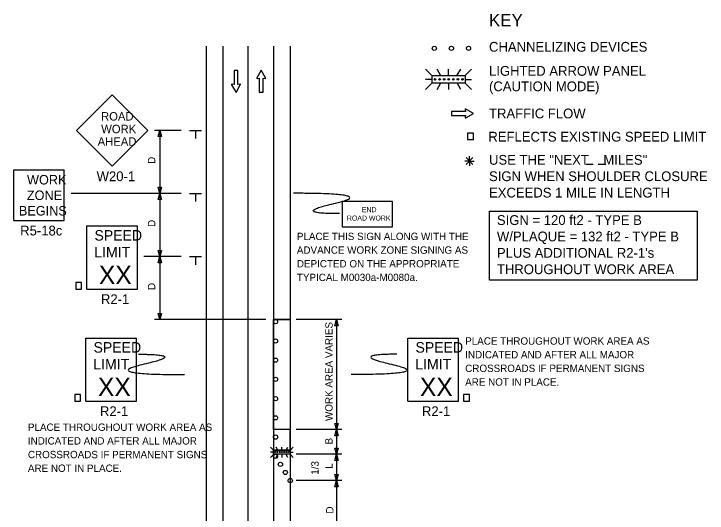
# Model space of a CAD drawing. Extents: x 16750 to 18471, y 7218 to 8211.
# Drawn here: x 16760 to 17420, y 7736 to 8211 of the extents above; entities that cross this region are included whole.
import ezdxf

# ---------------------------------------------------------------- set-up
doc = ezdxf.new("R2010")
doc.units = 0
for name, color, linetype in [('Level 6', 7, 'Continuous'), ('MT_SCRATCH_LEVEL_E', 7, 'Continuous'), ('PAVT_EDGE_EX', 7, 'Continuous'), ('TRAFFIC_SIGNS_PR', 7, 'Continuous'), ('TYPICAL_TEXT_DIMEN_EX', 7, 'Continuous'), ('TYPICAL_TEXT_DIMEN_PR', 7, 'Continuous')]:
    doc.layers.add(name, color=color, linetype=linetype)

msp = doc.modelspace()

# ---------------------------------------------------------------- linework, layer by layer
at = {"layer": 'Level 6'}
for points in [[(17191.74, 8091.59), (17197.33, 8091.59), (17197.33, 8097.76), (17191.74, 8097.76)], [(16819.11, 7949.45), (16824.71, 7949.45), (16824.71, 7955.62), (16819.11, 7955.62)], [(16818.21, 7842.9), (16823.8, 7842.9), (16823.8, 7849.07), (16818.21, 7849.07)], [(17188.08, 7842.9), (17193.67, 7842.9), (17193.67, 7849.07), (17188.08, 7849.07)]]:
    msp.add_lwpolyline(points, close=True, dxfattribs=at)
at = {"layer": 'MT_SCRATCH_LEVEL_E'}
for p, q in [((16973.41, 8157.34), (16969.67, 8157.34)), ((16969.67, 8157.34), (16969.67, 8144.08)), ((16973.41, 8157.34), (16969.67, 8157.34)), ((16969.67, 8157.34), (16969.67, 8144.08)), ((16973.41, 8144.08), (16973.41, 8157.34)), ((16973.41, 8144.08), (16973.41, 8157.34)), ((16995.57, 8157.71), (16991.46, 8150.47)), ((16995.57, 8157.71), (16991.46, 8150.47)), ((16999.72, 8150.47), (16995.57, 8157.71)), ((16999.72, 8150.47), (16995.57, 8157.71)), ((16967.42, 8143.72), (16971.56, 8136.47)), ((16967.42, 8143.72), (16971.56, 8136.47)), ((16969.67, 8144.08), (16967.9, 8144.4)), ((16969.67, 8144.08), (16967.9, 8144.4)), ((16971.56, 8136.47), (16975.67, 8143.72)), ((16971.56, 8136.47), (16975.67, 8143.72)), ((16975.19, 8144.4), (16973.41, 8144.08)), ((16975.19, 8144.4), (16973.41, 8144.08)), ((16991.94, 8149.79), (16993.72, 8150.1)), ((16991.94, 8149.79), (16993.72, 8150.1)), ((16993.72, 8150.1), (16993.72, 8136.85)), ((16993.72, 8150.1), (16993.72, 8136.85)), ((16997.46, 8136.85), (16997.46, 8150.1)), ((16997.46, 8150.1), (16999.24, 8149.79)), ((16997.46, 8136.85), (16997.46, 8150.1)), ((16997.46, 8150.1), (16999.24, 8149.79)), ((16993.72, 8136.85), (16997.46, 8136.85)), ((16993.72, 8136.85), (16997.46, 8136.85)), ((17189.75, 8118.42), (17176.5, 8118.42)), ((17176.5, 8118.42), (17176.5, 8114.68)), ((17189.75, 8118.42), (17176.5, 8118.42)), ((17176.5, 8118.42), (17176.5, 8114.68)), ((17189.44, 8120.2), (17189.75, 8118.42)), ((17189.44, 8120.2), (17189.75, 8118.42)), ((17197.36, 8116.57), (17190.12, 8120.68)), ((17197.36, 8116.57), (17190.12, 8120.68)), ((17176.5, 8114.68), (17189.75, 8114.68)), ((17176.5, 8114.68), (17189.75, 8114.68)), ((17189.75, 8114.68), (17189.44, 8112.9)), ((17189.75, 8114.68), (17189.44, 8112.9)), ((17190.12, 8112.42), (17197.36, 8116.57)), ((17190.12, 8112.42), (17197.36, 8116.57))]:
    msp.add_line(p, q, dxfattribs=at)
for centre, start, end in [((16991.87, 8150.25), 150.42484, 279.96381), ((16991.87, 8150.25), 150.42484, 279.96381), ((16999.31, 8150.25), 260.03619, 29.77312), ((16999.31, 8150.25), 260.03619, 29.77312), ((16967.82, 8143.94), 80.03619, 209.77312), ((16967.82, 8143.94), 80.03619, 209.77312), ((16975.27, 8143.94), 330.42484, 99.96381), ((16975.27, 8143.94), 330.42484, 99.96381), ((17189.9, 8120.27), 60.42484, 189.96381), ((17189.9, 8120.27), 60.42484, 189.96381), ((17189.9, 8112.83), 170.03619, 299.77312), ((17189.9, 8112.83), 170.03619, 299.77312)]:
    msp.add_arc(centre, 0.463, start, end, dxfattribs=at)
at = {"layer": 'PAVT_EDGE_EX'}
for p, q in [((16943.15, 8180.56), (16943.15, 7445.4)), ((16959.15, 8180.56), (16959.15, 7445.4)), ((16983.15, 7383.56), (16983.15, 8180.56)), ((17007.15, 8180.56), (17007.15, 7445.4)), ((17023.15, 8180.56), (17023.15, 7445.4)), ((17007.15, 7815.82), (17007.15, 7920.41)), ((17007.15, 7920.41), (17023.15, 7920.41)), ((17023.15, 7920.41), (17023.15, 7815.82)), ((17023.15, 7815.82), (17007.15, 7815.82)), ((17023.15, 7815.82), (17007.15, 7815.82)), ((17007.15, 7815.82), (17007.15, 7796.12)), ((17023.15, 7796.12), (17023.15, 7815.82)), ((17007.15, 7796.12), (17023.15, 7796.12))]:
    msp.add_line(p, q, dxfattribs=at)
for points in [[(16983.15, 8145.4), (16983.15, 8170.4)], [(16983.15, 8045.4), (16983.15, 8070.4)], [(16983.15, 7945.4), (16983.15, 7970.4)], [(16983.15, 7845.4), (16983.15, 7870.4)], [(16983.15, 7745.4), (16983.15, 7770.4)]]:
    msp.add_lwpolyline(points, dxfattribs=at)
at = {"layer": 'TRAFFIC_SIGNS_PR'}
for p, q in [((17151.95, 8158.61), (17157.59, 8152.98)), ((17166.13, 8152.98), (17162.87, 8158.62)), ((17173.76, 8152.98), (17173.76, 8158.62)), ((17182.03, 8152.98), (17185.28, 8158.62)), ((17189.93, 8152.98), (17195.57, 8158.62)), ((17157.59, 8148.91), (17151.95, 8148.91)), ((17151.95, 8139.21), (17157.59, 8144.85)), ((17160.86, 8148.91), (17160.86, 8148.91)), ((17162.82, 8139.21), (17166.07, 8144.85)), ((17165.21, 8148.91), (17165.21, 8148.91)), ((17169.56, 8148.91), (17169.56, 8148.91)), ((17173.76, 8144.85), (17173.76, 8139.21)), ((17173.91, 8148.91), (17173.91, 8148.91)), ((17178.25, 8148.91), (17178.25, 8148.91)), ((17185.33, 8139.21), (17182.08, 8144.85)), ((17182.6, 8148.91), (17182.6, 8148.91)), ((17186.95, 8148.91), (17186.95, 8148.91)), ((17189.93, 8148.91), (17195.57, 8148.91)), ((17189.93, 8144.85), (17195.57, 8139.21)), ((16853.79, 8134.25), (16819.85, 8100.31)), ((16887.73, 8100.31), (16853.79, 8134.25)), ((16819.85, 8100.31), (16853.79, 8066.37)), ((16853.79, 8066.37), (16887.73, 8100.31)), ((16760.27, 8014.73), (16760.27, 8062.73)), ((16760.27, 8062.73), (16808.27, 8062.73)), ((16808.27, 8014.73), (16808.27, 8062.73)), ((16760.27, 8014.73), (16808.27, 8014.73)), ((16829.72, 8009.45), (16877.72, 8009.45)), ((16829.72, 7949.45), (16829.72, 8009.45)), ((16877.72, 7949.45), (16877.72, 8009.45)), ((16829.72, 7949.45), (16877.72, 7949.45)), ((17023.15, 7920.41), (17007.15, 7920.41)), ((17009.15, 7918.39), (17009.15, 7918.39)), ((16828.82, 7902.9), (16876.82, 7902.9)), ((16828.82, 7842.9), (16828.82, 7902.9)), ((16876.82, 7842.9), (16876.82, 7902.9)), ((17135.06, 7902.9), (17183.06, 7902.9)), ((17135.06, 7842.9), (17135.06, 7902.9)), ((17183.06, 7842.9), (17183.06, 7902.9)), ((16828.82, 7842.9), (16876.82, 7842.9)), ((17135.06, 7842.9), (17183.06, 7842.9)), ((17023.15, 7815.82), (17007.15, 7815.82)), ((17004.26, 7799.07), (17007.08, 7796.25)), ((17007.08, 7794.22), (17004.26, 7794.22)), ((17023.15, 7796.12), (17007.15, 7796.12)), ((17008.72, 7794.22), (17008.72, 7794.22)), ((17011.35, 7796.25), (17009.72, 7799.07)), ((17010.9, 7794.22), (17010.9, 7794.22)), ((17013.07, 7794.22), (17013.07, 7794.22)), ((17015.17, 7796.25), (17015.17, 7799.07)), ((17015.24, 7794.22), (17015.24, 7794.22)), ((17017.42, 7794.22), (17017.42, 7794.22)), ((17019.3, 7796.25), (17020.93, 7799.07)), ((17019.59, 7794.22), (17019.59, 7794.22)), ((17021.76, 7794.22), (17021.76, 7794.22)), ((17023.25, 7796.25), (17026.08, 7799.07)), ((17023.25, 7794.22), (17026.08, 7794.22)), ((17004.26, 7789.37), (17007.08, 7792.19)), ((17009.7, 7789.37), (17011.33, 7792.19)), ((17015.17, 7792.19), (17015.17, 7789.37)), ((17020.96, 7789.37), (17019.33, 7792.19)), ((17023.25, 7792.19), (17026.08, 7789.37))]:
    msp.add_line(p, q, dxfattribs=at)
for points in [[(17189.47, 8145.31), (17158.05, 8145.31), (17158.05, 8152.51), (17189.47, 8152.51)], [(17072.52, 8008.67), (17120.52, 8008.67), (17120.52, 8032.67), (17072.52, 8032.67)], [(17023.02, 7792.42), (17007.32, 7792.42), (17007.32, 7796.02), (17023.02, 7796.02)]]:
    msp.add_lwpolyline(points, close=True, dxfattribs=at)
for centre, radius in [((17160.15, 8178.49), 2), ((17176.45, 8178.49), 2), ((17192.75, 8178.49), 2), ((17160.9, 8148.91), 0.758), ((17165.21, 8148.91), 0.758), ((17169.56, 8148.91), 0.758), ((17173.9, 8148.91), 0.758), ((17178.25, 8148.91), 0.758), ((17182.6, 8148.91), 0.758), ((17186.95, 8148.91), 0.758), ((17009.15, 7918.39), 2), ((17009.15, 7900.1), 2), ((17009.15, 7881.81), 2), ((17009.15, 7863.53), 2), ((17009.15, 7845.24), 2), ((17009.15, 7826.96), 2), ((17009.15, 7808.67), 2), ((17008.74, 7794.22), 0.379), ((17010.89, 7794.22), 0.379), ((17013.07, 7794.22), 0.379), ((17015.24, 7794.22), 0.379), ((17017.42, 7794.22), 0.379), ((17019.59, 7794.22), 0.379), ((17021.76, 7794.22), 0.379), ((17009.14, 7790.38), 2), ((17009.15, 7790.39), 2), ((17013.81, 7782.69), 2), ((17018.48, 7774.99), 2), ((17023.15, 7767.3), 2)]:
    msp.add_circle(centre, radius, dxfattribs=at)
for points in [[(17069.87, 8021.22), (17022.64, 8021.22), (17107.66, 8040.56), (17026.18, 8040.56)], [(16878.89, 7887.45), (16926.12, 7887.45), (16841.1, 7868.11), (16922.58, 7868.11)], [(17124.66, 7887.45), (17077.43, 7887.45), (17162.45, 7868.11), (17080.97, 7868.11)]]:
    msp.add_open_spline(points, degree=2, dxfattribs=at)
at = {"layer": 'TYPICAL_TEXT_DIMEN_PR'}
for p, q in [((16919.43, 8100.41), (16894.15, 8100.41)), ((16897.58, 8094.55), (16899.15, 8100.41)), ((16899.15, 8100.41), (16900.73, 8094.55)), ((16899.15, 8100.41), (16899.15, 8040.41)), ((16927.47, 8100.41), (16938.72, 8100.41)), ((16933.1, 8100.41), (16933.1, 8092.63)), ((16899.15, 8094.55), (16897.58, 8094.55)), ((16900.73, 8094.55), (16899.15, 8094.55)), ((17193.6, 8071.26), (17189.07, 8071.26)), ((17190.41, 8074.45), (17196.79, 8068.07)), ((17196.79, 8074.45), (17190.41, 8068.07)), ((17193.6, 8071.26), (17193.6, 8075.72)), ((17193.6, 8071.26), (17196.79, 8071.26)), ((17193.6, 8071.26), (17198.08, 8071.26)), ((17193.6, 8071.26), (17193.6, 8066.76)), ((17304.21, 8068.26), (17311.21, 8068.26)), ((17316.16, 8068.1), (17323.16, 8068.1)), ((16899.15, 8040.41), (16897.58, 8046.28)), ((16897.58, 8046.28), (16899.15, 8046.28)), ((16899.15, 8046.28), (16900.73, 8046.28)), ((16900.73, 8046.28), (16899.15, 8040.41)), ((16919.43, 8040.41), (16814.69, 8040.41)), ((16897.58, 8034.55), (16899.15, 8040.41)), ((16899.15, 8040.41), (16900.73, 8034.55)), ((16899.15, 8040.41), (16899.15, 7980.41)), ((16927.47, 8040.41), (16938.72, 8040.41)), ((16933.1, 8040.41), (16933.1, 8032.63)), ((16899.15, 8034.55), (16897.58, 8034.55)), ((16900.73, 8034.55), (16899.15, 8034.55)), ((16899.15, 7980.41), (16897.58, 7986.28)), ((16897.58, 7986.28), (16899.15, 7986.28)), ((16899.15, 7986.28), (16900.73, 7986.28)), ((16900.73, 7986.28), (16899.15, 7980.41)), ((16919.43, 7980.41), (16883.8, 7980.41)), ((16897.58, 7974.55), (16899.15, 7980.41)), ((16899.15, 7980.41), (16900.73, 7974.55)), ((16899.15, 7980.03), (16899.15, 7920.41)), ((16927.47, 7980.41), (16938.72, 7980.41)), ((16933.1, 7980.41), (16933.1, 7972.63)), ((16899.15, 7974.55), (16897.58, 7974.55)), ((16900.73, 7974.55), (16899.15, 7974.55)), ((16899.15, 7920.41), (16897.58, 7926.28)), ((16897.58, 7926.28), (16899.15, 7926.28)), ((16899.15, 7920.41), (16897.58, 7926.28)), ((16897.58, 7926.28), (16899.15, 7926.28)), ((16899.15, 7926.28), (16900.73, 7926.28)), ((16900.73, 7926.28), (16899.15, 7920.41)), ((16899.15, 7926.28), (16900.73, 7926.28)), ((16900.73, 7926.28), (16899.15, 7920.41)), ((16999.85, 7920.41), (16894.15, 7920.41)), ((17072.15, 7920.39), (17028.88, 7920.39)), ((17065.58, 7914.52), (17067.15, 7920.39)), ((17067.15, 7920.39), (17067.15, 7815.82)), ((17067.15, 7920.39), (17068.73, 7914.52)), ((17067.15, 7914.52), (17065.58, 7914.52)), ((17068.73, 7914.52), (17067.15, 7914.52)), ((17067.15, 7815.82), (17065.58, 7821.69)), ((17065.58, 7821.69), (17067.15, 7821.69)), ((17067.15, 7821.69), (17068.73, 7821.69)), ((17068.73, 7821.69), (17067.15, 7815.82)), ((17072.15, 7815.82), (17028.88, 7815.82)), ((17065.58, 7809.96), (17067.15, 7815.82)), ((17065.58, 7809.96), (17067.15, 7815.82)), ((17067.15, 7815.82), (17067.15, 7792.39)), ((17067.15, 7815.82), (17068.73, 7809.96)), ((17067.15, 7815.82), (17068.73, 7809.96)), ((17067.15, 7809.96), (17065.58, 7809.96)), ((17067.15, 7809.96), (17065.58, 7809.96)), ((17068.73, 7809.96), (17067.15, 7809.96)), ((17068.73, 7809.96), (17067.15, 7809.96)), ((17067.15, 7792.39), (17065.58, 7798.25)), ((17065.58, 7798.25), (17067.15, 7798.25)), ((17067.15, 7798.25), (17068.73, 7798.25)), ((17068.73, 7798.25), (17067.15, 7792.39)), ((17072.15, 7792.39), (17028.88, 7792.39)), ((17065.58, 7786.53), (17067.15, 7792.39)), ((17067.15, 7792.39), (17067.15, 7767.3)), ((17067.15, 7792.39), (17068.73, 7786.53)), ((17067.15, 7786.53), (17065.58, 7786.53)), ((17068.73, 7786.53), (17067.15, 7786.53)), ((17067.15, 7767.3), (17065.58, 7773.16)), ((17065.58, 7773.16), (17067.15, 7773.16)), ((17067.15, 7773.16), (17068.73, 7773.16)), ((17068.73, 7773.16), (17067.15, 7767.3)), ((17072.15, 7767.3), (17028.88, 7767.3)), ((17065.58, 7761.44), (17067.15, 7767.3)), ((17067.15, 7761.44), (17065.58, 7761.44)), ((17067.15, 7767.3), (17068.73, 7761.44)), ((17067.15, 7767.3), (17067.15, 7707.85)), ((17068.73, 7761.44), (17067.15, 7761.44))]:
    msp.add_line(p, q, dxfattribs=at)
msp.add_lwpolyline([(17212.79, 8023.58), (17410.07, 8023.58), (17410.07, 7958.04), (17212.79, 7958.04)], close=True, dxfattribs=at)

# ---------------------------------------------------------------- texts
at = {"layer": 'TRAFFIC_SIGNS_PR'}
for s, height, p in [('ROAD', 8, (16843.21, 8109.73)), ('WORK', 8, (16843.35, 8097.73)), ('AHEAD', 8, (16839.99, 8085.73)), ('WORK', 9.021, (16772.77, 8048.94)), ('W20-1', 9.3, (16839, 8052.07)), ('ZONE', 9.021, (16772.62, 8034.18)), ('BEGINS', 9.021, (16765.03, 8019.42)), ('END', 4.789, (17091.27, 8022.58)), ('ROAD WORK', 4.789, (17077.03, 8014.6)), ('R5-18c', 9.3, (16766.28, 8000.43)), ('SPEED', 10, (16836.93, 7995.53)), ('PLACE THIS SIGN ALONG WITH THE', 7, (17029.46, 7996.06)), ('LIMIT', 10, (16836.73, 7979.53)), ('ADVANCE WORK ZONE SIGNING AS', 7, (17029.46, 7983.06)), ('DEPICTED ON THE APPROPRIATE', 7, (17029.46, 7970.06)), ('XX', 17.538, (16841.11, 7954.15)), ('TYPICAL M0030a-M0080a.', 7, (17029.46, 7957.06)), ('R2-1', 9.3, (16843.07, 7935.15)), ('PLACE THROUGHOUT WORK AREA AS', 7, (17189.55, 7896.56)), ('SPEED', 10, (16836.03, 7888.98)), ('SPEED', 10, (17142.27, 7888.98)), ('INDICATED AND AFTER ALL MAJOR', 7, (17189.55, 7883.56)), ('LIMIT', 10, (16835.82, 7872.98)), ('LIMIT', 10, (17142.07, 7872.98)), ('CROSSROADS IF PERMANENT SIGNS', 7, (17189.55, 7870.56)), ('XX', 17.538, (16840.21, 7847.6)), ('XX', 17.538, (17146.45, 7847.6)), ('ARE NOT IN PLACE.', 7, (17189.55, 7857.56)), ('R2-1', 9.3, (16842.16, 7828.6)), ('R2-1', 9.3, (17148.41, 7828.6)), ('PLACE THROUGHOUT WORK AREA AS', 7, (16773.64, 7814.55)), ('INDICATED AND AFTER ALL MAJOR', 7, (16773.64, 7801.55)), ('CROSSROADS IF PERMANENT SIGNS', 7, (16773.64, 7788.55)), ('ARE NOT IN PLACE.', 7, (16773.64, 7775.55))]:
    msp.add_text(s, height=height, dxfattribs=at).set_placement(p)
at = {"layer": 'TYPICAL_TEXT_DIMEN_EX'}
for s, height, p in [('KEY', 12, (17212.21, 8199.23)), ('CHANNELIZING DEVICES', 9.3, (17212.21, 8175.23)), ('LIGHTED ARROW PANEL', 9.3, (17212.21, 8152.33)), ('(CAUTION MODE)', 9.3, (17212.21, 8137.63)), ('TRAFFIC FLOW', 9.3, (17212.21, 8111.83))]:
    msp.add_text(s, height=height, dxfattribs=at).set_placement(p)
at = {"layer": 'TYPICAL_TEXT_DIMEN_PR'}
for s, p in [('REFLECTS EXISTING SPEED LIMIT', (17211.57, 8089.75)), ('USE THE "NEXT    MILES"', (17212.21, 8067.73)), ('SIGN WHEN SHOULDER CLOSURE', (17212.21, 8052.13)), ('EXCEEDS 1 MILE IN LENGTH', (17212.21, 8036.53)), ('SIGN = 120 ft2 - TYPE B', (17219.72, 8010.44)), ('W/PLAQUE = 132 ft2 - TYPE B', (17219.72, 7994.84)), ("PLUS ADDITIONAL R2-1's", (17219.72, 7979.24)), ('THROUGHOUT WORK AREA', (17219.72, 7963.64))]:
    msp.add_text(s, height=9.3, dxfattribs=at).set_placement(p)
for s, p in [('D', (16894.78, 8068.55)), ('D', (16894.78, 8008.55)), ('D', (16894.78, 7948.55)), ('WORK AREA VARIES', (17063.44, 7823.97)), ('B', (17063.44, 7801.67)), ('1/3', (17050.14, 7772.81)), ('L', (17063.44, 7778.6)), ('D', (17064.19, 7735.9))]:
    msp.add_text(s, height=7, rotation=90, dxfattribs=at).set_placement(p)

doc.saveas('drawing.dxf')
